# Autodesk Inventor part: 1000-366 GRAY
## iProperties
Created: 2007-03
Part Number: 1000-366 GRAY
Document SubType Name: Modeling
Designer: Andy Moles
Material: Steel
Mass: 101.663 g
Surface Area: 87.3571 cm^2
Volume: 12.9506 cm^3
Density: 7.85 g/cm^3
Author: Andy Moles
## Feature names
1. Base1
